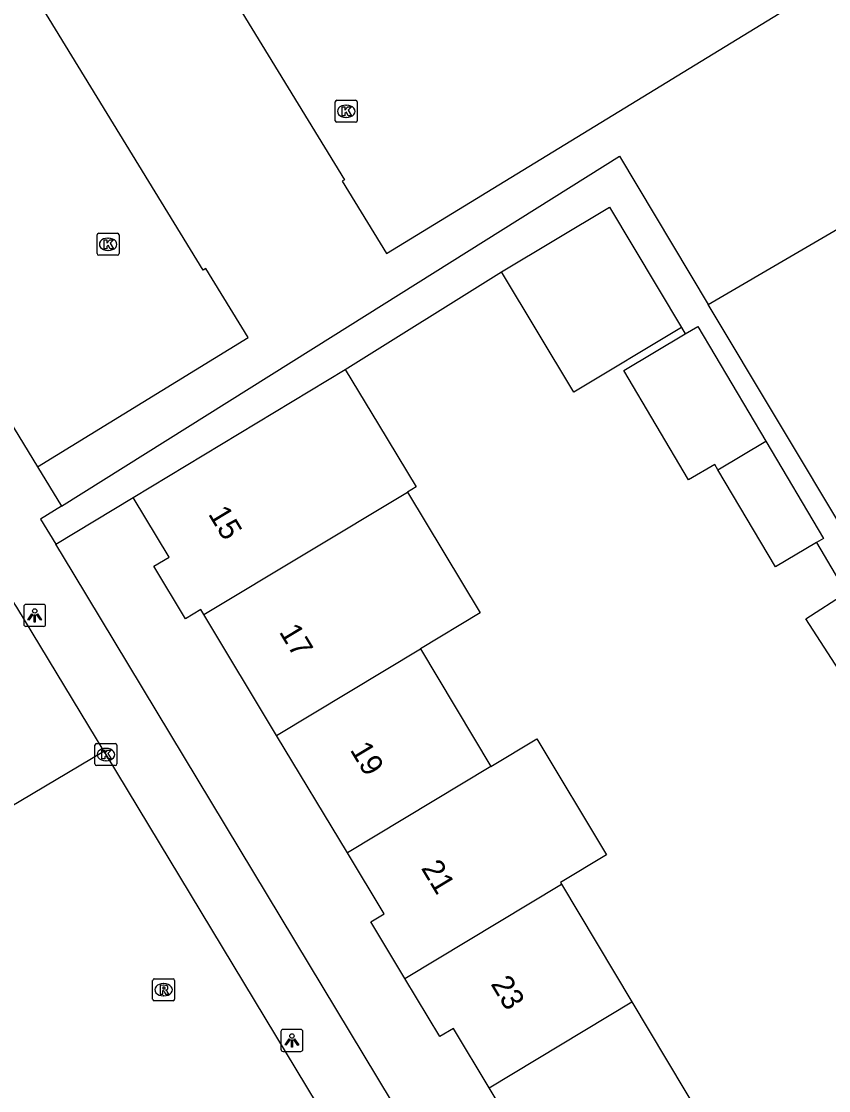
# Model space of a CAD drawing. Extents: x 159888 to 160757, y 384031 to 384746.
# Drawn here: x 160325.03 to 160361.8, y 384601.84 to 384650.52 of the extents above; entities that cross this region are included whole.
import ezdxf

# ---------------------------------------------------------------- set-up
doc = ezdxf.new("R2010")
doc.units = 0
for name, color, linetype in [('IMGEO_Kolk', 7, 'Continuous'), ('IMGEO_Lichtpunt', 7, 'Continuous'), ('IMGEO_Pand', 7, 'Continuous'), ('IMGEO_Pand_nummerreeks', 7, 'Continuous'), ('IMGEO_Rijbaan_lokaal_open', 7, 'Continuous'), ('IMGEO_Rioolput', 7, 'Continuous'), ('IMGEO_Voetpad_open', 7, 'Continuous')]:
    doc.layers.add(name, color=color, linetype=linetype)

msp = doc.modelspace()

# ---------------------------------------------------------------- linework, layer by layer
at = {"layer": 'IMGEO_Kolk'}
for p, q in [((160339.325, 384645.997), (160339.325, 384646.849)), ((160339.4, 384646.923), (160340.252, 384646.923)), ((160339.813, 384646.703), (160339.838, 384646.703)), ((160340.326, 384646.849), (160340.326, 384645.997)), ((160339.836, 384646.143), (160339.811, 384646.143)), ((160340.252, 384645.923), (160339.4, 384645.923)), ((160328.48, 384639.943), (160328.48, 384640.795)), ((160328.555, 384640.869), (160329.407, 384640.869)), ((160329.481, 384640.795), (160329.481, 384639.943)), ((160328.968, 384640.649), (160328.993, 384640.649)), ((160329.407, 384639.869), (160328.555, 384639.869)), ((160328.991, 384640.089), (160328.966, 384640.089)), ((160328.38, 384616.715), (160328.38, 384617.567)), ((160328.455, 384617.641), (160329.307, 384617.641)), ((160328.868, 384617.421), (160328.893, 384617.421)), ((160329.381, 384617.567), (160329.381, 384616.715)), ((160328.891, 384616.861), (160328.866, 384616.861)), ((160329.307, 384616.641), (160328.455, 384616.641))]:
    msp.add_line(p, q, dxfattribs=at)
for points in [[(160339.325, 384645.997), (160339.325, 384646.849)], [(160339.4, 384646.923), (160340.252, 384646.923)], [(160339.646, 384646.623), (160339.769, 384646.623), (160339.769, 384646.472), (160339.899, 384646.623), (160340.063, 384646.623), (160339.917, 384646.472), (160340.07, 384646.223), (160339.918, 384646.223), (160339.833, 384646.387), (160339.769, 384646.32), (160339.769, 384646.223), (160339.646, 384646.223), (160339.646, 384646.623)], [(160340.326, 384646.849), (160340.326, 384645.997)], [(160340.252, 384645.923), (160339.4, 384645.923)], [(160328.48, 384639.943), (160328.48, 384640.795)], [(160328.555, 384640.869), (160329.407, 384640.869)], [(160329.481, 384640.795), (160329.481, 384639.943)], [(160328.801, 384640.569), (160328.924, 384640.569), (160328.924, 384640.418), (160329.054, 384640.569), (160329.218, 384640.569), (160329.072, 384640.418), (160329.225, 384640.169), (160329.073, 384640.169), (160328.988, 384640.333), (160328.924, 384640.266), (160328.924, 384640.169), (160328.801, 384640.169), (160328.801, 384640.569)], [(160329.407, 384639.869), (160328.555, 384639.869)], [(160328.38, 384616.715), (160328.38, 384617.567)], [(160328.455, 384617.641), (160329.307, 384617.641)], [(160328.701, 384617.341), (160328.824, 384617.341), (160328.824, 384617.19), (160328.954, 384617.341), (160329.118, 384617.341), (160328.972, 384617.19), (160329.125, 384616.941), (160328.973, 384616.941), (160328.888, 384617.105), (160328.824, 384617.038), (160328.824, 384616.941), (160328.701, 384616.941), (160328.701, 384617.341)], [(160329.381, 384617.567), (160329.381, 384616.715)], [(160329.307, 384616.641), (160328.455, 384616.641)]]:
    msp.add_lwpolyline(points, dxfattribs=at)
for centre, start, end in [((160339.402, 384646.847), 91.552, 178.448), ((160339.402, 384646.847), 91.552, 178.448), ((160340.25, 384646.847), 1.552, 88.448), ((160340.25, 384646.847), 1.552, 88.448), ((160339.402, 384645.999), 181.552, 268.448), ((160339.402, 384645.999), 181.552, 268.448), ((160340.25, 384645.999), 271.552, 358.448), ((160340.25, 384645.999), 271.552, 358.448), ((160328.557, 384640.793), 91.552, 178.448), ((160328.557, 384640.793), 91.552, 178.448), ((160329.405, 384640.793), 1.552, 88.448), ((160329.405, 384640.793), 1.552, 88.448), ((160328.557, 384639.945), 181.552, 268.448), ((160328.557, 384639.945), 181.552, 268.448), ((160329.405, 384639.945), 271.552, 358.448), ((160329.405, 384639.945), 271.552, 358.448), ((160328.457, 384617.565), 91.552, 178.448), ((160328.457, 384617.565), 91.552, 178.448), ((160329.305, 384617.565), 1.552, 88.448), ((160329.305, 384617.565), 1.552, 88.448), ((160328.457, 384616.717), 181.552, 268.448), ((160328.457, 384616.717), 181.552, 268.448), ((160329.305, 384616.717), 271.552, 358.448), ((160329.305, 384616.717), 271.552, 358.448)]:
    msp.add_arc(centre, 0.0765, start, end, dxfattribs=at)
for centre, major_axis, ratio, start_param, end_param in [((160339.812, 384646.423), (-0.387, 0.002), 0.722429, 4.712389, 7.853982), ((160339.837, 384646.423), (-0.39, 0.002), 0.717154, 1.570796, 4.712389), ((160328.967, 384640.369), (-0.387, 0.002), 0.722429, 4.712389, 7.853982), ((160328.992, 384640.369), (-0.39, 0.002), 0.717154, 1.570796, 4.712389), ((160328.867, 384617.141), (-0.387, 0.002), 0.722429, 4.712389, 7.853982), ((160328.892, 384617.141), (-0.39, 0.002), 0.717154, 1.570796, 4.712389)]:
    msp.add_ellipse(centre, major_axis=major_axis, ratio=ratio, start_param=start_param, end_param=end_param, dxfattribs=at)
at = {"layer": 'IMGEO_Lichtpunt'}
for p, q in [((160325.137, 384623.88), (160325.137, 384623.073)), ((160325.137, 384623.88), (160325.137, 384623.073)), ((160326.039, 384623.975), (160325.231, 384623.975)), ((160326.039, 384623.975), (160325.231, 384623.975)), ((160326.133, 384623.073), (160326.133, 384623.88)), ((160326.133, 384623.073), (160326.133, 384623.88)), ((160325.231, 384622.979), (160326.039, 384622.979)), ((160325.231, 384622.979), (160326.039, 384622.979)), ((160336.853, 384604.533), (160336.853, 384603.726)), ((160336.853, 384604.533), (160336.853, 384603.726)), ((160337.755, 384604.628), (160336.947, 384604.628)), ((160337.755, 384604.628), (160336.947, 384604.628)), ((160337.849, 384603.726), (160337.849, 384604.533)), ((160337.849, 384603.726), (160337.849, 384604.533)), ((160336.947, 384603.632), (160337.755, 384603.632)), ((160336.947, 384603.632), (160337.755, 384603.632))]:
    msp.add_line(p, q, dxfattribs=at)
for points in [[(160325.511, 384623.544), (160325.55, 384623.516), (160325.362, 384623.254), (160325.324, 384623.281), (160325.511, 384623.544)], [(160325.613, 384623.496), (160325.66, 384623.496), (160325.66, 384623.174), (160325.613, 384623.174), (160325.613, 384623.496)], [(160325.723, 384623.516), (160325.761, 384623.543), (160325.948, 384623.281), (160325.909, 384623.253), (160325.723, 384623.516)], [(160337.227, 384604.197), (160337.266, 384604.169), (160337.078, 384603.907), (160337.04, 384603.934), (160337.227, 384604.197)], [(160337.439, 384604.169), (160337.477, 384604.196), (160337.664, 384603.934), (160337.625, 384603.906), (160337.439, 384604.169)], [(160337.329, 384604.149), (160337.376, 384604.149), (160337.376, 384603.827), (160337.329, 384603.827), (160337.329, 384604.149)]]:
    msp.add_lwpolyline(points, dxfattribs=at)
for centre in [(160325.636, 384623.678), (160337.352, 384604.331)]:
    msp.add_circle(centre, 0.0994, dxfattribs=at)
for centre, start, end in [((160325.231, 384623.88), 90, 180), ((160325.231, 384623.88), 90, 180), ((160326.039, 384623.88), 0, 90), ((160326.039, 384623.88), 0, 90), ((160325.231, 384623.073), 180, 270), ((160325.231, 384623.073), 180, 270), ((160326.039, 384623.073), 270, 0), ((160326.039, 384623.073), 270, 360), ((160336.947, 384604.533), 90, 180), ((160336.947, 384604.533), 90, 180), ((160337.755, 384604.533), 0, 90), ((160337.755, 384604.533), 0, 90), ((160336.947, 384603.726), 180, 270), ((160336.947, 384603.726), 180, 270), ((160337.755, 384603.726), 270, 0), ((160337.755, 384603.726), 270, 360)]:
    msp.add_arc(centre, 0.0946, start, end, dxfattribs=at)
at = {"layer": 'IMGEO_Pand'}
for points in [[(160309.591, 384656.709), (160319.073, 384662.433), (160315.085, 384668.871), (160316.903, 384669.997), (160318.133, 384668.013), (160320.98, 384669.778), (160318.707, 384673.447), (160320.567, 384674.588), (160339.751, 384643.307), (160339.64, 384643.239), (160341.658, 384639.949), (160376.616, 384661.318), (160366.48, 384678.151), (160340.8, 384662.717), (160326.989, 384685.697), (160303.563, 384671.457), (160306.422, 384666.806), (160304.243, 384665.466)], [(160356.321, 384637.631), (160364.49, 384642.391), (160367.445, 384644.113), (160385.679, 384649.677), (160366.762, 384680.819), (160373.345, 384684.923)], [(160325.759, 384630.237), (160335.353, 384636.124), (160333.428, 384639.261), (160333.317, 384639.193), (160322.198, 384657.311), (160312.719, 384651.588)], [(160312.719, 384651.588), (160313.133, 384650.91), (160314.471, 384648.719), (160319.784, 384640.021), (160321.118, 384637.836), (160325.759, 384630.237)], [(160346.907, 384639.116), (160351.812, 384642.056), (160355.093, 384636.584)], [(160355.093, 384636.584), (160350.187, 384633.644), (160346.907, 384639.116)], [(160362.672, 384627.03), (160356.321, 384637.631)], [(160355.267, 384636.29), (160355.842, 384636.631), (160358.939, 384631.412)], [(160356.76, 384630.102), (160356.614, 384630.347), (160355.425, 384629.642), (160352.467, 384634.629), (160355.267, 384636.29)], [(160330.122, 384628.85), (160339.784, 384634.676)], [(160339.784, 384634.676), (160341.297, 384632.167), (160343.008, 384629.329), (160342.615, 384629.092)], [(160356.76, 384630.102), (160358.939, 384631.412)], [(160358.939, 384631.412), (160361.569, 384626.978), (160361.249, 384626.788)], [(160361.249, 384626.788), (160359.383, 384625.681), (160356.76, 384630.102)], [(160333.34, 384623.511), (160342.615, 384629.092)], [(160342.615, 384629.092), (160345.927, 384623.586), (160343.207, 384621.949)], [(160333.34, 384623.511), (160333.197, 384623.748), (160332.498, 384623.327), (160331.061, 384625.711), (160331.76, 384626.133), (160330.122, 384628.85)], [(160363.261, 384619.446), (160360.766, 384623.327), (160362.602, 384624.507)], [(160336.657, 384618.009), (160333.34, 384623.511)], [(160336.657, 384618.009), (160343.207, 384621.949)], [(160343.207, 384621.949), (160346.417, 384616.597)], [(160339.88, 384612.664), (160336.657, 384618.009)], [(160346.417, 384616.597), (160348.508, 384617.855), (160351.683, 384612.578), (160349.584, 384611.315), (160349.627, 384611.243)], [(160346.417, 384616.597), (160339.88, 384612.664)], [(160342.498, 384606.954), (160340.947, 384609.527), (160341.551, 384609.892), (160339.88, 384612.664)], [(160342.498, 384606.954), (160349.627, 384611.243)], [(160349.627, 384611.243), (160352.838, 384605.889)], [(160346.334, 384601.977), (160344.717, 384604.674), (160344.098, 384604.301), (160342.498, 384606.954)], [(160346.334, 384601.977), (160352.838, 384605.889)], [(160352.838, 384605.889), (160356.047, 384600.536)], [(160349.544, 384596.624), (160346.334, 384601.977)]]:
    msp.add_lwpolyline(points, dxfattribs=at)
at = {"layer": 'IMGEO_Rijbaan_lokaal_open'}
for points in [[(160295.444, 384672.163), (160296.254, 384670.824), (160298.109, 384667.759), (160306.181, 384654.411), (160307.199, 384652.736), (160310.692, 384646.906), (160320.969, 384630.093), (160324.715, 384623.983), (160324.799, 384623.845), (160328.781, 384617.284)], [(160328.781, 384617.284), (160322.819, 384613.753)], [(160328.781, 384617.284), (160328.88, 384617.141), (160339.964, 384598.8)]]:
    msp.add_lwpolyline(points, dxfattribs=at)
at = {"layer": 'IMGEO_Rioolput'}
for p, q in [((160331.009, 384606.012), (160331.009, 384606.864)), ((160331.084, 384606.938), (160331.936, 384606.938)), ((160331.497, 384606.718), (160331.522, 384606.718)), ((160332.01, 384606.864), (160332.01, 384606.012)), ((160331.52, 384606.158), (160331.495, 384606.158)), ((160331.936, 384605.938), (160331.084, 384605.938))]:
    msp.add_line(p, q, dxfattribs=at)
for points in [[(160331.009, 384606.012), (160331.009, 384606.864)], [(160331.084, 384606.938), (160331.936, 384606.938)], [(160331.598, 384606.636), (160331.346, 384606.638), (160331.346, 384606.238)], [(160332.01, 384606.864), (160332.01, 384606.012)], [(160331.346, 384606.238), (160331.47, 384606.238), (160331.47, 384606.4), (160331.481, 384606.4)], [(160331.524, 384606.557), (160331.47, 384606.557), (160331.47, 384606.476)], [(160331.47, 384606.476), (160331.522, 384606.476)], [(160331.528, 384606.371), (160331.599, 384606.238), (160331.739, 384606.238), (160331.674, 384606.364)], [(160331.936, 384605.938), (160331.084, 384605.938)]]:
    msp.add_lwpolyline(points, dxfattribs=at)
for centre, radius, start, end in [((160331.086, 384606.862), 0.0765, 91.552, 178.448), ((160331.086, 384606.862), 0.0765, 91.552, 178.448), ((160331.597, 384606.526), 0.109, 350.3612, 89.416), ((160331.934, 384606.862), 0.0765, 1.552, 88.448), ((160331.934, 384606.862), 0.0765, 1.552, 88.448), ((160331.48, 384606.347), 0.0533, 26.0293, 88.6989), ((160331.506, 384606.665), 0.19, 274.7715, 282.9687), ((160331.53, 384606.461), 0.0964, 77.0061, 93.1865), ((160331.544, 384606.518), 0.0378, 276.6634, 79.6772), ((160331.595, 384606.526), 0.112, 277.5842, 350.9817), ((160331.579, 384606.311), 0.108, 29.5134, 73.7905), ((160331.086, 384606.014), 0.0765, 181.552, 268.448), ((160331.086, 384606.014), 0.0765, 181.552, 268.448), ((160331.934, 384606.014), 0.0765, 271.552, 358.448), ((160331.934, 384606.014), 0.0765, 271.552, 358.448)]:
    msp.add_arc(centre, radius, start, end, dxfattribs=at)
for centre, major_axis, ratio, start_param, end_param in [((160331.496, 384606.438), (-0.387, 0.002), 0.722429, 4.712389, 7.853982), ((160331.521, 384606.438), (-0.39, 0.002), 0.717154, 1.570796, 4.712389)]:
    msp.add_ellipse(centre, major_axis=major_axis, ratio=ratio, start_param=start_param, end_param=end_param, dxfattribs=at)
at = {"layer": 'IMGEO_Voetpad_open'}
for points in [[(160326.852, 384628.447), (160339.229, 384636.205), (160352.276, 384644.383), (160356.321, 384637.631)], [(160339.784, 384634.676), (160346.907, 384639.116)], [(160355.093, 384636.584), (160355.267, 384636.29)], [(160325.759, 384630.237), (160326.852, 384628.447)], [(160326.591, 384626.72), (160330.122, 384628.85)], [(160326.852, 384628.447), (160325.907, 384627.855), (160326.591, 384626.72)], [(160378.5, 384540.702), (160327.382, 384625.41), (160326.591, 384626.72)], [(160361.249, 384626.788), (160362.602, 384624.507)]]:
    msp.add_lwpolyline(points, dxfattribs=at)

# ---------------------------------------------------------------- texts
at = {"layer": 'IMGEO_Pand_nummerreeks'}
for s, rotation, p in [('15', 301.0302, (160333.517, 384628.095)), ('17', 301.0302, (160336.746, 384622.728)), ('19', 301.0302, (160339.975, 384617.36)), ('21', 301.0312, (160343.215, 384611.974)), ('23', 301.0302, (160346.386, 384606.703))]:
    msp.add_text(s, height=1, rotation=rotation, dxfattribs=at).set_placement(p)

doc.saveas('drawing.dxf')
